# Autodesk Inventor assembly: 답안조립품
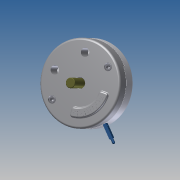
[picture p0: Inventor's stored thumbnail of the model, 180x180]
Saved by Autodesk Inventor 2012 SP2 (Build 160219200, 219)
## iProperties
Created: 2015-04
Part Number: 답안조립품
Document SubType Name: Assembly
Designer: Administrator
Author: Administrator
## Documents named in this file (10)
- C:\Users\Administrator\Desktop\450406V1005\답안조립품.iam
- C:\Users\Administrator\Desktop\450406V1005\1-본체.ipt
- C:\Users\Administrator\Desktop\450406V1005\축.ipt
- C:\Users\Administrator\Desktop\450406V1005\베어링62_22.ipt
- C:\Users\Administrator\Desktop\450406V1005\멈춤링.ipt
- C:\Users\Administrator\Desktop\450406V1005\슬라이더.ipt
- C:\Users\Administrator\Desktop\450406V1005\슬라이더2.ipt
- C:\Users\Administrator\Desktop\450406V1005\평행핀.ipt
- C:\Users\Administrator\Desktop\450406V1005\덮개.ipt
- C:\Users\Administrator\Desktop\450406V1005\M 10 x 35.ipt
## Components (3 placed, 2 different names)
1. 1-본체:1 — 각도:1
2. M 10 x 35:1
3. M 10 x 35:2
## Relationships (1: Angle 1)
- 각도:1 [Angle]: 1-본체:1
